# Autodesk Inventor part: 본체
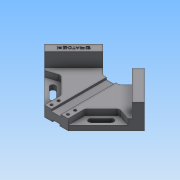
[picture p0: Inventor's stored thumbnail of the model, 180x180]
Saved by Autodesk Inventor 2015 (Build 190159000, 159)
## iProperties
Created: 2019-04
Part Number: 본체
Material: 일반
Document SubType Name: Modeling
Designer: SCD-A01
Density: 1 g/cm^3
Appearance: 기본값
Author: SCD-A01
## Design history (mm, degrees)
sketch "스케치3"
  geometry: L1 (84.853, 0)-(0, -84.853); L2 (0, -84.853)-(-84.853, 0); L3 (-84.853, 0)-(0, 84.853); L4 (0, 84.853)-(84.853, 0); L5 (42.426, -42.426)-(-42.426, 42.426); L6 (-60, -60)-(60, 60); 3 further points
  constraints: 12 end point, 4 midpoint, 3 parallel, 2 vertical alignment, 1 perpendicular
  dimensions: "d6" = 120 distance of L2.end L3.end; "d7" = 120 distance of L1.end L2.end; "d8" = 60 distance from line of point (0, 0) L4
extrude "돌출2" new body sketch "스케치3" distance "d9" = 18; taper "d10" = 0 deg
sketch "스케치4"
  geometry: L1 (0, -84.853)-(84.853, 0) reference; L2 (-84.853, 0)-(0, -84.853) reference; L3 (-40.47, -64.853)-(52.354, -64.853); L4 (-40.47, -64.853)-(-40.47, -87.492); L5 (-40.47, -87.492)-(52.354, -87.492); L6 (52.354, -87.492)-(52.354, -64.853); 1 further point
  constraints: 8 end point, 2 perpendicular, 1 horizontal, 1 vertical
  dimensions: "d11" = 20 distance from line of L1.start L3; "d12" = 92.82402 distance between parallel lines of L4 L6; "d13" = 22.63922 distance between parallel lines of L3 L5
extrude "돌출3" cut sketch "스케치4" distance "d14" = 18; taper "d15" = 0 deg
sketch "스케치6"
  geometry: L1 (84.853, 0)-(0, 84.853) reference; L2 (0, 84.853)-(-84.853, 0) reference; L3 (-84.853, 0)-(-20, -64.853) reference; L4 (-84.853, 0)-(-74.246, -10.607); L5 (-74.246, -10.607)-(10.607, 74.246); L6 (10.607, 74.246)-(0, 84.853); L7 (-84.853, 0)-(0, 84.853); 1 further point
  constraints: 8 end point, 2 point on line, 1 perpendicular
  dimensions: "d17" = 15 distance between parallel lines of L5 L2
extrude "돌출4" join sketch "스케치6" distance "d18" = 24; taper "d19" = 0 deg
sketch "스케치7"
  geometry: L1 (20, -64.853)-(84.853, 0) reference; L2 (84.853, 0)-(10.607, 74.246) reference; L3 (20, -64.853)-(-20, -64.853) reference; L4 (-20, -64.853)-(-74.246, -10.607) reference; L5 (10.607, 74.246)-(-74.246, -10.607) reference; L6 (0, 84.853)-(10.607, 74.246) reference; L7 (-84.853, 0)-(0, 84.853) reference; L8 (-74.246, -10.607)-(-84.853, 0) reference; L9 (84.853, 0)-(20, -64.853) reference; L10 (10.607, 74.246)-(84.853, 0) reference; L11 (84.853, 0)-(0, 84.853); L12 (0, 84.853)-(-10.607, 74.246); L13 (84.853, 0)-(74.246, -10.607); L14 (-10.607, 74.246)-(74.246, -10.607); 1 further point
  constraints: 8 end point, 2 collinear, 2 point on line, 1 perpendicular
  dimensions: "d21" = 15 distance between parallel lines of L2 L14
extrude "돌출5" join sketch "스케치7" distance "d22" = 24; taper "d23" = 0 deg
sketch "스케치8"
  geometry: L1 (0, 84.853)-(-84.853, 0) reference; L2 (0, 84.853)-(-35.355, 49.497); L3 (-35.355, 49.497)-(-14, 28.147); L4 (-14, 28.147)-(0, 28.147); L5 (0, 28.147)-(0, 84.853); L6 (-20, -64.853)-(20, -64.853) reference; 1 further point
  constraints: 8 end point, 1 horizontal, 1 perpendicular, 1 point on line
  dimensions: "d24" = 50 distance of L1.start L2.end; "d25" = 93 distance between parallel lines of L6 L4; "d27" = 14 distance of L3.end L4.end
extrude "돌출6" cut sketch "스케치8" stored distance "d28" = 24; taper "d29" = 0 deg
sketch "스케치9"
  geometry: L1 (40, -18)-(0, -18) reference; L2 (0, 0)-(40, 0) reference; L3 (12, 0)-(28, 0); L4 (28, 0)-(28, -3.5); L5 (28, -3.5)-(12, -3.5); L6 (12, -3.5)-(12, 0); 3 further points
  constraints: 8 end point, 2 midpoint, 2 parallel, 1 collinear, 1 horizontal, 1 perpendicular, 1 vertical alignment
  dimensions: "d30" = 16 distance of L4.end L5.end; "d31" = 3.5 distance of L3.end L4.end
extrude "돌출7" cut sketch "스케치9" stored distance "d32" = 24; taper "d33" = 0 deg
sketch "스케치10"
  geometry: L1 (40, 0)-(0, 0) reference; L2 (14, 3)-(26, 3); L3 (26, 3)-(26, 0); L4 (26, 0)-(14, 0); L5 (14, 0)-(14, 3); 2 further points
  constraints: 8 end point, 2 midpoint, 2 parallel, 1 collinear, 1 horizontal, 1 perpendicular
  dimensions: "d34" = 12 distance of L3.end L4.end; "d35" = 3 distance of L2.end L3.end
extrude "돌출8" cut sketch "스케치10" stored distance "d36" = 24; taper "d37" = 0 deg
sketch "스케치12"
  geometry: L1 (-8, -64.853)-(-8, 28.147) reference; L2 (-35.355, 49.497)-(-84.853, 0) reference; L3 (0, 0)-(0, -91.058); L4 (-70.711, -14.142)-(-49.497, -7.071); L5 (-49.497, -7.071)-(-20, -36.569); L6 (-20, -36.569)-(-20, -64.853); L7 (-20, -64.853)-(-70.711, -14.142); L8 (-74.246, -10.607)-(-20, -64.853) reference
  constraints: 10 end point, 2 parallel, 1 collinear, 1 vertical
  dimensions: "d43" = 20 distance from line of L8 L4.end; "d44" = 20 distance from line of L2 L4.start; "d45" = 20 distance from line of L3 L6.end; "d46" = 30 distance from line of L2 L4.end
extrude "돌출9" cut sketch "스케치12" distance "d47" = 10; taper "d48" = 0 deg
sketch "스케치15"
  geometry: L1 (-20, -64.853)-(-70.711, -14.142) reference; L2 (-49.497, -21.213)-(-32.527, -38.184); L3 (-52.679, -24.395)-(-35.709, -41.366); L4 (-29.345, -35.002)-(-46.315, -18.031); L5 (-49.497, -21.213)-(-25.497, -21.213); L6 (-35.355, 49.497)-(-84.853, 0) reference; A1 r 4.5 centre (-49.497, -21.213) between (-46.315, -18.031) and (-52.679, -24.395); A2 r 4.5 centre (-32.527, -38.184) between (-35.709, -41.366) and (-29.345, -35.002); 2 further points
  constraints: 10 end point, 4 point on circle, 4 tangent, 2 centre point, 1 equal length, 1 horizontal, 1 midpoint, 1 parallel
  dimensions: "d56" = 24 distance of L2.start L2.end; "d57" = 45 deg angle of L2 L5; "d58" = 9 diameter of A2; "d59" = 40 distance from line of L6 L2.start; "d60" = 10 distance from line of L1 L2.start
extrude "돌출10" cut sketch "스케치15" stored distance "d61" = 10; taper "d62" = 0 deg
sketch "스케치17"
  geometry: L1 (6, -64.853)-(20, -64.853) reference; L2 (0, 0)-(0, -60.396); 1 further point
  constraints: 2 end point, 1 vertical
  dimensions: "d64" = 6 distance from line of point (14, -58.853) L1; "d65" = 14 distance from line of L2 point (14, -58.853)
hole "구멍1" sketch "스케치17" at (14, -58.853) diameter "d66" = 4.5; stored, may be unused: countersink angle "d70" = 90 deg, drill point angle "d72" = 118 deg; dims "d67" = 6, "d68" = 8, "d69" = 10, "d71" = 8
fillet "모깎기1" dims "d76" = 5
fillet "모깎기2" dims "d77" = 5
sketch "스케치19"
  geometry: L1 (-24.747, 38.892)-(-35.355, 49.497) reference; L2 (-35.355, 49.497)-(-84.853, 0) reference; 2 further points
  constraints: 1 other
  dimensions: "d78" = 7.5 distance from line of L2 point (-54.8, 19.446); "d79" = 35 distance from line of L1 point (-54.8, 19.446)
feature "엠보싱1" sketch "스케치19" dims "d80" = 0.5, "d81" = 0
node "솔리드2"
mirror "대칭1"
mirror "대칭2"
mirror "대칭3"
pattern_linear "직사각형 패턴1" dims "d75" = 12
mirror "대칭4"
node "절단 모서리 투영1"
